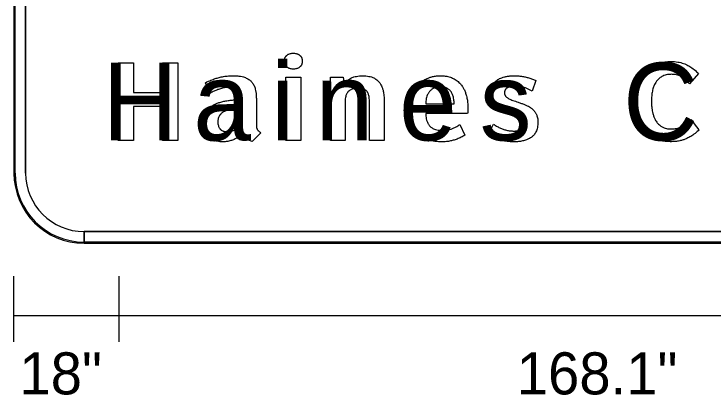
# Model space of a CAD drawing. Extents: x 10268259 to 10268554, y 2141099 to 2141249.
# Drawn here: x 10268434.65 to 10268446.62, y 2141129.23 to 2141135.75 of the extents above; entities that cross this region are included whole.
import ezdxf

# ---------------------------------------------------------------- set-up
doc = ezdxf.new("R2010")
doc.units = 0
for name, color, linetype in [('GSBWFill', 7, 'Continuous'), ('GSColorFill', 7, 'Continuous'), ('GSDims', 7, 'Continuous'), ('GSOutline', 7, 'Continuous')]:
    doc.layers.add(name, color=color, linetype=linetype)

msp = doc.modelspace()

# ---------------------------------------------------------------- linework, layer by layer
at = {"layer": 'GSBWFill'}
for p, q in [((10268434.654, 2141148.028), (10268434.654, 2141133.028)), ((10268434.854, 2141133.028), (10268434.854, 2141148.028)), ((10268435.854, 2141131.828), (10268435.854, 2141132.028)), ((10268453.854, 2141132.028), (10268435.856, 2141132.028)), ((10268435.856, 2141132.028), (10268435.856, 2141131.828)), ((10268435.856, 2141131.828), (10268453.854, 2141131.828))]:
    msp.add_line(p, q, dxfattribs=at)
for radius in [1.2, 1]:
    msp.add_arc((10268435.854, 2141133.028), radius, 180, 270, dxfattribs=at)
at = {"layer": 'GSColorFill'}
for p, q in [((10268434.654, 2141148.028), (10268434.654, 2141133.028)), ((10268434.654, 2141148.028), (10268434.654, 2141133.028)), ((10268434.654, 2141148.028), (10268434.654, 2141133.028)), ((10268434.674, 2141133.028), (10268434.674, 2141148.028)), ((10268434.854, 2141133.028), (10268434.854, 2141148.028)), ((10268435.854, 2141131.828), (10268435.854, 2141132.028)), ((10268453.854, 2141132.028), (10268435.856, 2141132.028)), ((10268435.856, 2141132.028), (10268435.856, 2141131.828)), ((10268435.854, 2141131.828), (10268435.854, 2141131.848)), ((10268453.854, 2141131.848), (10268435.855, 2141131.848)), ((10268435.855, 2141131.848), (10268435.855, 2141131.828)), ((10268435.854, 2141131.828), (10268453.854, 2141131.828)), ((10268435.855, 2141131.828), (10268453.854, 2141131.828)), ((10268435.856, 2141131.828), (10268453.854, 2141131.828))]:
    msp.add_line(p, q, dxfattribs=at)
for radius in [1.2, 1.2, 1.2, 1.18, 1]:
    msp.add_arc((10268435.854, 2141133.028), radius, 180, 270, dxfattribs=at)
at = {"layer": 'GSDims'}
for p, q in [((10268434.654, 2141130.139), (10268434.654, 2141131.264)), ((10268436.454, 2141130.139), (10268436.454, 2141131.264)), ((10268434.654, 2141130.589), (10268455.054, 2141130.589))]:
    msp.add_line(p, q, dxfattribs=at)
at = {"layer": 'GSOutline'}
for p, q in [((10268434.654, 2141148.028), (10268434.654, 2141133.028)), ((10268434.854, 2141148.028), (10268434.854, 2141133.028)), ((10268435.854, 2141132.028), (10268453.854, 2141132.028)), ((10268435.854, 2141131.828), (10268453.854, 2141131.828))]:
    msp.add_line(p, q, dxfattribs=at)
for points in [[(10268437.199, 2141133.588), (10268437.199, 2141134.167), (10268436.698, 2141134.167), (10268436.698, 2141133.588), (10268436.438, 2141133.588), (10268436.438, 2141134.918), (10268436.698, 2141134.918), (10268436.698, 2141134.411), (10268437.199, 2141134.411), (10268437.199, 2141134.918), (10268437.457, 2141134.918), (10268437.457, 2141133.588), (10268437.199, 2141133.588)], [(10268446.37, 2141134.735), (10268446.213, 2141134.559)], [(10268439.308, 2141133.588), (10268439.308, 2141134.674), (10268439.563, 2141134.674), (10268439.563, 2141133.588), (10268439.308, 2141133.588)], [(10268440.321, 2141134.246), (10268440.321, 2141133.588), (10268440.069, 2141133.588), (10268440.069, 2141134.674), (10268440.288, 2141134.674), (10268440.308, 2141134.553), (10268440.312, 2141134.553)], [(10268443.586, 2141134.612), (10268443.521, 2141134.432)], [(10268438.005, 2141134.393), (10268437.93, 2141134.576)], [(10268438.555, 2141134.286), (10268438.555, 2141134.335)], [(10268438.803, 2141134.294), (10268438.803, 2141133.861)], [(10268440.991, 2141134.242), (10268440.991, 2141133.588), (10268440.739, 2141133.588)], [(10268438.552, 2141133.841), (10268438.552, 2141134.133)], [(10268440.739, 2141133.588), (10268440.739, 2141134.203)], [(10268441.702, 2141134.214), (10268442.187, 2141134.214)], [(10268442.419, 2141134.048), (10268441.702, 2141134.048)], [(10268446.238, 2141133.945), (10268446.376, 2141133.768)], [(10268442.284, 2141133.859), (10268442.368, 2141133.677)], [(10268442.77, 2141133.686), (10268442.86, 2141133.865)], [(10268438.579, 2141133.7), (10268438.575, 2141133.7)], [(10268438.882, 2141133.72), (10268438.731, 2141133.572)]]:
    msp.add_lwpolyline(points, dxfattribs=at)
for radius in [1.2, 1]:
    msp.add_arc((10268435.854, 2141133.028), radius, 180, 270, dxfattribs=at)
for points in [[(10268439.282, 2141134.946), (10268439.282, 2141134.951), (10268439.282, 2141134.963), (10268439.285, 2141134.979), (10268439.29, 2141134.995), (10268439.295, 2141135.007), (10268439.301, 2141135.019), (10268439.309, 2141135.03), (10268439.316, 2141135.038), (10268439.323, 2141135.044), (10268439.33, 2141135.05), (10268439.339, 2141135.057), (10268439.358, 2141135.068), (10268439.384, 2141135.077), (10268439.413, 2141135.081), (10268439.43, 2141135.081), (10268439.435, 2141135.082)], [(10268439.435, 2141135.082), (10268439.441, 2141135.081), (10268439.457, 2141135.081), (10268439.483, 2141135.077), (10268439.505, 2141135.07), (10268439.521, 2141135.063), (10268439.531, 2141135.057), (10268439.54, 2141135.05), (10268439.547, 2141135.044), (10268439.554, 2141135.038), (10268439.562, 2141135.03), (10268439.569, 2141135.019), (10268439.576, 2141135.007), (10268439.581, 2141134.995), (10268439.586, 2141134.979), (10268439.589, 2141134.963), (10268439.589, 2141134.951), (10268439.589, 2141134.946)], [(10268439.435, 2141134.81), (10268439.43, 2141134.81), (10268439.413, 2141134.81), (10268439.387, 2141134.814), (10268439.365, 2141134.821), (10268439.349, 2141134.828), (10268439.339, 2141134.834), (10268439.33, 2141134.84), (10268439.323, 2141134.846), (10268439.316, 2141134.852), (10268439.309, 2141134.86), (10268439.301, 2141134.871), (10268439.295, 2141134.883), (10268439.289, 2141134.895), (10268439.285, 2141134.911), (10268439.282, 2141134.928), (10268439.282, 2141134.941), (10268439.282, 2141134.946)], [(10268439.589, 2141134.946), (10268439.589, 2141134.941), (10268439.589, 2141134.928), (10268439.586, 2141134.911), (10268439.581, 2141134.895), (10268439.576, 2141134.883), (10268439.569, 2141134.871), (10268439.562, 2141134.86), (10268439.554, 2141134.852), (10268439.547, 2141134.846), (10268439.54, 2141134.84), (10268439.529, 2141134.832), (10268439.51, 2141134.822), (10268439.483, 2141134.814), (10268439.457, 2141134.81), (10268439.441, 2141134.81), (10268439.435, 2141134.81)], [(10268445.292, 2141134.259), (10268445.293, 2141134.282), (10268445.294, 2141134.351), (10268445.307, 2141134.442), (10268445.329, 2141134.527), (10268445.354, 2141134.597), (10268445.386, 2141134.662), (10268445.42, 2141134.713), (10268445.445, 2141134.744), (10268445.471, 2141134.774), (10268445.507, 2141134.808), (10268445.556, 2141134.844), (10268445.599, 2141134.87), (10268445.636, 2141134.888), (10268445.676, 2141134.904), (10268445.74, 2141134.924), (10268445.82, 2141134.937), (10268445.88, 2141134.939), (10268445.905, 2141134.939)], [(10268445.905, 2141134.939), (10268445.927, 2141134.939), (10268445.961, 2141134.938), (10268446.015, 2141134.931), (10268446.066, 2141134.921), (10268446.116, 2141134.905), (10268446.154, 2141134.89), (10268446.221, 2141134.857), (10268446.295, 2141134.805), (10268446.352, 2141134.751), (10268446.37, 2141134.735)], [(10268445.91, 2141134.72), (10268445.897, 2141134.719), (10268445.863, 2141134.718), (10268445.818, 2141134.711), (10268445.777, 2141134.698), (10268445.744, 2141134.683), (10268445.714, 2141134.665), (10268445.687, 2141134.643), (10268445.667, 2141134.621), (10268445.652, 2141134.603), (10268445.638, 2141134.582), (10268445.618, 2141134.549), (10268445.594, 2141134.491), (10268445.575, 2141134.41), (10268445.566, 2141134.329), (10268445.565, 2141134.277), (10268445.565, 2141134.258)], [(10268446.213, 2141134.559), (10268446.202, 2141134.572), (10268446.169, 2141134.607), (10268446.121, 2141134.647), (10268446.078, 2141134.676), (10268446.048, 2141134.692), (10268446.016, 2141134.705), (10268445.976, 2141134.715), (10268445.94, 2141134.719), (10268445.918, 2141134.719), (10268445.91, 2141134.72)], [(10268437.93, 2141134.576), (10268437.969, 2141134.594), (10268438.026, 2141134.621), (10268438.103, 2141134.648), (10268438.161, 2141134.665), (10268438.24, 2141134.684), (10268438.322, 2141134.694), (10268438.385, 2141134.695), (10268438.406, 2141134.695)], [(10268438.406, 2141134.695), (10268438.424, 2141134.695), (10268438.472, 2141134.694), (10268438.535, 2141134.687), (10268438.584, 2141134.674), (10268438.615, 2141134.663), (10268438.644, 2141134.651), (10268438.675, 2141134.632), (10268438.698, 2141134.614), (10268438.714, 2141134.598), (10268438.73, 2141134.581), (10268438.747, 2141134.558), (10268438.764, 2141134.526), (10268438.775, 2141134.498), (10268438.784, 2141134.467), (10268438.795, 2141134.418), (10268438.802, 2141134.357), (10268438.802, 2141134.311), (10268438.803, 2141134.294)], [(10268440.312, 2141134.553), (10268440.316, 2141134.559), (10268440.33, 2141134.578), (10268440.355, 2141134.607), (10268440.388, 2141134.635), (10268440.418, 2141134.654), (10268440.444, 2141134.665), (10268440.471, 2141134.674), (10268440.513, 2141134.686), (10268440.566, 2141134.694), (10268440.604, 2141134.695), (10268440.62, 2141134.695)], [(10268440.62, 2141134.695), (10268440.638, 2141134.695), (10268440.678, 2141134.694), (10268440.732, 2141134.686), (10268440.774, 2141134.674), (10268440.799, 2141134.664), (10268440.822, 2141134.653), (10268440.849, 2141134.638), (10268440.878, 2141134.615), (10268440.899, 2141134.593), (10268440.914, 2141134.574), (10268440.928, 2141134.553), (10268440.943, 2141134.526), (10268440.961, 2141134.483), (10268440.974, 2141134.437), (10268440.988, 2141134.354), (10268440.99, 2141134.291), (10268440.991, 2141134.242)], [(10268441.444, 2141134.13), (10268441.444, 2141134.154), (10268441.445, 2141134.219), (10268441.457, 2141134.294), (10268441.474, 2141134.353), (10268441.486, 2141134.389), (10268441.507, 2141134.439), (10268441.538, 2141134.492), (10268441.569, 2141134.532), (10268441.592, 2141134.557), (10268441.615, 2141134.579), (10268441.646, 2141134.605), (10268441.687, 2141134.631), (10268441.723, 2141134.649), (10268441.762, 2141134.664), (10268441.818, 2141134.682), (10268441.886, 2141134.694), (10268441.938, 2141134.695), (10268441.955, 2141134.695)], [(10268441.955, 2141134.695), (10268441.974, 2141134.695), (10268442.019, 2141134.694), (10268442.079, 2141134.684), (10268442.128, 2141134.669), (10268442.158, 2141134.657), (10268442.186, 2141134.643), (10268442.22, 2141134.624), (10268442.256, 2141134.596), (10268442.284, 2141134.569), (10268442.304, 2141134.546), (10268442.323, 2141134.521), (10268442.35, 2141134.48), (10268442.375, 2141134.426), (10268442.394, 2141134.368), (10268442.412, 2141134.295), (10268442.422, 2141134.216), (10268442.423, 2141134.155), (10268442.423, 2141134.134)], [(10268442.808, 2141134.388), (10268442.808, 2141134.394), (10268442.809, 2141134.412), (10268442.812, 2141134.44), (10268442.818, 2141134.473), (10268442.827, 2141134.499), (10268442.836, 2141134.518), (10268442.846, 2141134.537), (10268442.86, 2141134.559), (10268442.88, 2141134.583), (10268442.9, 2141134.602), (10268442.917, 2141134.615), (10268442.935, 2141134.628), (10268442.965, 2141134.646), (10268443.003, 2141134.662), (10268443.045, 2141134.675), (10268443.099, 2141134.688), (10268443.157, 2141134.694), (10268443.201, 2141134.695), (10268443.216, 2141134.695)], [(10268443.216, 2141134.695), (10268443.232, 2141134.695), (10268443.28, 2141134.694), (10268443.343, 2141134.687), (10268443.405, 2141134.676), (10268443.467, 2141134.661), (10268443.528, 2141134.639), (10268443.571, 2141134.619), (10268443.586, 2141134.612)], [(10268438.387, 2141134.503), (10268438.37, 2141134.503), (10268438.32, 2141134.502), (10268438.253, 2141134.491), (10268438.188, 2141134.474), (10268438.125, 2141134.452), (10268438.063, 2141134.425), (10268438.02, 2141134.401), (10268438.005, 2141134.393)], [(10268438.555, 2141134.335), (10268438.555, 2141134.342), (10268438.554, 2141134.362), (10268438.551, 2141134.392), (10268438.544, 2141134.418), (10268438.537, 2141134.435), (10268438.531, 2141134.446), (10268438.525, 2141134.456), (10268438.519, 2141134.463), (10268438.513, 2141134.47), (10268438.503, 2141134.477), (10268438.49, 2141134.485), (10268438.473, 2141134.492), (10268438.446, 2141134.499), (10268438.416, 2141134.503), (10268438.395, 2141134.503), (10268438.387, 2141134.503)], [(10268440.547, 2141134.482), (10268440.538, 2141134.482), (10268440.511, 2141134.481), (10268440.473, 2141134.476), (10268440.439, 2141134.466), (10268440.416, 2141134.455), (10268440.398, 2141134.444), (10268440.385, 2141134.434), (10268440.375, 2141134.424), (10268440.366, 2141134.414), (10268440.356, 2141134.4), (10268440.346, 2141134.382), (10268440.336, 2141134.358), (10268440.326, 2141134.322), (10268440.321, 2141134.283), (10268440.321, 2141134.255), (10268440.321, 2141134.246)], [(10268440.739, 2141134.203), (10268440.739, 2141134.223), (10268440.739, 2141134.26), (10268440.736, 2141134.306), (10268440.731, 2141134.343), (10268440.725, 2141134.37), (10268440.717, 2141134.391), (10268440.711, 2141134.404), (10268440.704, 2141134.416), (10268440.694, 2141134.43), (10268440.679, 2141134.444), (10268440.665, 2141134.454), (10268440.653, 2141134.462), (10268440.639, 2141134.468), (10268440.619, 2141134.475), (10268440.587, 2141134.481), (10268440.563, 2141134.482), (10268440.547, 2141134.482)], [(10268441.956, 2141134.505), (10268441.946, 2141134.504), (10268441.923, 2141134.504), (10268441.892, 2141134.499), (10268441.863, 2141134.491), (10268441.84, 2141134.481), (10268441.818, 2141134.47), (10268441.798, 2141134.456), (10268441.782, 2141134.442), (10268441.77, 2141134.43), (10268441.759, 2141134.417), (10268441.747, 2141134.4), (10268441.734, 2141134.377), (10268441.721, 2141134.347), (10268441.709, 2141134.304), (10268441.703, 2141134.258), (10268441.702, 2141134.226), (10268441.702, 2141134.214)], [(10268442.187, 2141134.214), (10268442.187, 2141134.224), (10268442.186, 2141134.253), (10268442.182, 2141134.291), (10268442.175, 2141134.327), (10268442.167, 2141134.361), (10268442.155, 2141134.388), (10268442.143, 2141134.41), (10268442.137, 2141134.42), (10268442.127, 2141134.433), (10268442.114, 2141134.448), (10268442.096, 2141134.463), (10268442.08, 2141134.474), (10268442.065, 2141134.482), (10268442.05, 2141134.489), (10268442.029, 2141134.496), (10268441.996, 2141134.503), (10268441.971, 2141134.504), (10268441.956, 2141134.505)], [(10268443.235, 2141134.518), (10268443.222, 2141134.517), (10268443.192, 2141134.517), (10268443.151, 2141134.51), (10268443.12, 2141134.5), (10268443.104, 2141134.493), (10268443.093, 2141134.487), (10268443.084, 2141134.481), (10268443.074, 2141134.472), (10268443.065, 2141134.462), (10268443.059, 2141134.451), (10268443.054, 2141134.439), (10268443.051, 2141134.425), (10268443.049, 2141134.413), (10268443.049, 2141134.406), (10268443.049, 2141134.403)], [(10268443.521, 2141134.432), (10268443.51, 2141134.439), (10268443.478, 2141134.458), (10268443.433, 2141134.479), (10268443.385, 2141134.495), (10268443.337, 2141134.509), (10268443.286, 2141134.516), (10268443.248, 2141134.517), (10268443.235, 2141134.518)], [(10268443.138, 2141134.054), (10268443.118, 2141134.061), (10268443.079, 2141134.074), (10268443.03, 2141134.092), (10268442.983, 2141134.113), (10268442.948, 2141134.134), (10268442.919, 2141134.155), (10268442.9, 2141134.171), (10268442.882, 2141134.188), (10268442.859, 2141134.215), (10268442.843, 2141134.241), (10268442.828, 2141134.27), (10268442.819, 2141134.296), (10268442.812, 2141134.331), (10268442.809, 2141134.362), (10268442.808, 2141134.381), (10268442.808, 2141134.388)], [(10268443.049, 2141134.403), (10268443.049, 2141134.4), (10268443.049, 2141134.393), (10268443.051, 2141134.38), (10268443.056, 2141134.366), (10268443.062, 2141134.355), (10268443.068, 2141134.347), (10268443.074, 2141134.339), (10268443.086, 2141134.328), (10268443.101, 2141134.316), (10268443.124, 2141134.302), (10268443.154, 2141134.287), (10268443.193, 2141134.272), (10268443.236, 2141134.258), (10268443.265, 2141134.248), (10268443.281, 2141134.243)], [(10268437.896, 2141133.893), (10268437.896, 2141133.907), (10268437.897, 2141133.928), (10268437.901, 2141133.961), (10268437.907, 2141133.992), (10268437.916, 2141134.021), (10268437.928, 2141134.047), (10268437.939, 2141134.067), (10268437.954, 2141134.091), (10268437.971, 2141134.113), (10268437.99, 2141134.133), (10268438.01, 2141134.152), (10268438.041, 2141134.177), (10268438.081, 2141134.201), (10268438.134, 2141134.225), (10268438.191, 2141134.245), (10268438.263, 2141134.262), (10268438.336, 2141134.274), (10268438.41, 2141134.282), (10268438.483, 2141134.286), (10268438.531, 2141134.286), (10268438.555, 2141134.286)], [(10268443.281, 2141134.243), (10268443.301, 2141134.236), (10268443.341, 2141134.223), (10268443.391, 2141134.204), (10268443.44, 2141134.183), (10268443.477, 2141134.162), (10268443.507, 2141134.14), (10268443.527, 2141134.124), (10268443.545, 2141134.106), (10268443.566, 2141134.082), (10268443.58, 2141134.06), (10268443.591, 2141134.042), (10268443.601, 2141134.022), (10268443.61, 2141133.995), (10268443.618, 2141133.959), (10268443.621, 2141133.927), (10268443.621, 2141133.907), (10268443.621, 2141133.9)], [(10268445.905, 2141133.566), (10268445.879, 2141133.566), (10268445.818, 2141133.568), (10268445.735, 2141133.581), (10268445.67, 2141133.6), (10268445.63, 2141133.617), (10268445.592, 2141133.634), (10268445.548, 2141133.66), (10268445.5, 2141133.696), (10268445.465, 2141133.73), (10268445.439, 2141133.76), (10268445.414, 2141133.791), (10268445.381, 2141133.842), (10268445.35, 2141133.908), (10268445.327, 2141133.979), (10268445.306, 2141134.068), (10268445.294, 2141134.162), (10268445.293, 2141134.234), (10268445.292, 2141134.259)], [(10268445.565, 2141134.258), (10268445.566, 2141134.227), (10268445.567, 2141134.179), (10268445.575, 2141134.118), (10268445.583, 2141134.074), (10268445.596, 2141134.019), (10268445.615, 2141133.969), (10268445.637, 2141133.928), (10268445.654, 2141133.902), (10268445.674, 2141133.878), (10268445.7, 2141133.852), (10268445.725, 2141133.834), (10268445.746, 2141133.821), (10268445.769, 2141133.809), (10268445.8, 2141133.797), (10268445.841, 2141133.788), (10268445.877, 2141133.784), (10268445.9, 2141133.784), (10268445.908, 2141133.784)], [(10268438.552, 2141134.133), (10268438.531, 2141134.133), (10268438.486, 2141134.132), (10268438.43, 2141134.128), (10268438.373, 2141134.122), (10268438.328, 2141134.113), (10268438.291, 2141134.101), (10268438.266, 2141134.091), (10268438.243, 2141134.079), (10268438.217, 2141134.062), (10268438.198, 2141134.046), (10268438.185, 2141134.033), (10268438.177, 2141134.023), (10268438.17, 2141134.013), (10268438.158, 2141133.993), (10268438.148, 2141133.964), (10268438.144, 2141133.932), (10268438.143, 2141133.914), (10268438.143, 2141133.908)], [(10268441.968, 2141133.564), (10268441.948, 2141133.565), (10268441.898, 2141133.566), (10268441.831, 2141133.576), (10268441.777, 2141133.592), (10268441.743, 2141133.604), (10268441.711, 2141133.618), (10268441.674, 2141133.639), (10268441.633, 2141133.667), (10268441.601, 2141133.695), (10268441.578, 2141133.719), (10268441.557, 2141133.744), (10268441.532, 2141133.778), (10268441.502, 2141133.831), (10268441.479, 2141133.889), (10268441.456, 2141133.971), (10268441.445, 2141134.049), (10268441.444, 2141134.109), (10268441.444, 2141134.13)], [(10268442.423, 2141134.134), (10268442.423, 2141134.128), (10268442.423, 2141134.115), (10268442.422, 2141134.094), (10268442.421, 2141134.072), (10268442.42, 2141134.056), (10268442.419, 2141134.048)], [(10268441.702, 2141134.048), (10268441.702, 2141134.036), (10268441.703, 2141134.004), (10268441.71, 2141133.954), (10268441.724, 2141133.912), (10268441.737, 2141133.883), (10268441.748, 2141133.864), (10268441.76, 2141133.847), (10268441.771, 2141133.834), (10268441.783, 2141133.822), (10268441.799, 2141133.808), (10268441.821, 2141133.794), (10268441.849, 2141133.78), (10268441.892, 2141133.767), (10268441.938, 2141133.76), (10268441.97, 2141133.76), (10268441.982, 2141133.76)], [(10268443.377, 2141133.881), (10268443.377, 2141133.884), (10268443.377, 2141133.893), (10268443.375, 2141133.907), (10268443.37, 2141133.923), (10268443.364, 2141133.935), (10268443.357, 2141133.944), (10268443.35, 2141133.952), (10268443.338, 2141133.965), (10268443.322, 2141133.978), (10268443.298, 2141133.993), (10268443.267, 2141134.008), (10268443.227, 2141134.024), (10268443.183, 2141134.039), (10268443.153, 2141134.049), (10268443.138, 2141134.054)], [(10268438.22, 2141133.564), (10268438.208, 2141133.564), (10268438.173, 2141133.565), (10268438.132, 2141133.572), (10268438.1, 2141133.582), (10268438.085, 2141133.587), (10268438.065, 2141133.595), (10268438.042, 2141133.607), (10268438.017, 2141133.624), (10268437.997, 2141133.64), (10268437.983, 2141133.654), (10268437.969, 2141133.668), (10268437.954, 2141133.688), (10268437.935, 2141133.719), (10268437.919, 2141133.753), (10268437.905, 2141133.801), (10268437.897, 2141133.846), (10268437.896, 2141133.881), (10268437.896, 2141133.893)], [(10268438.143, 2141133.908), (10268438.143, 2141133.902), (10268438.144, 2141133.885), (10268438.147, 2141133.857), (10268438.157, 2141133.826), (10268438.168, 2141133.803), (10268438.179, 2141133.788), (10268438.187, 2141133.779), (10268438.195, 2141133.77), (10268438.207, 2141133.761), (10268438.22, 2141133.753), (10268438.235, 2141133.747), (10268438.253, 2141133.742), (10268438.273, 2141133.739), (10268438.288, 2141133.739), (10268438.295, 2141133.739)], [(10268443.206, 2141133.748), (10268443.212, 2141133.748), (10268443.231, 2141133.749), (10268443.261, 2141133.752), (10268443.293, 2141133.759), (10268443.314, 2141133.768), (10268443.327, 2141133.776), (10268443.333, 2141133.779), (10268443.34, 2141133.785), (10268443.348, 2141133.792), (10268443.356, 2141133.803), (10268443.363, 2141133.814), (10268443.369, 2141133.827), (10268443.374, 2141133.843), (10268443.377, 2141133.862), (10268443.377, 2141133.875), (10268443.377, 2141133.881)], [(10268443.621, 2141133.9), (10268443.621, 2141133.886), (10268443.62, 2141133.853), (10268443.613, 2141133.808), (10268443.601, 2141133.766), (10268443.588, 2141133.734), (10268443.571, 2141133.705), (10268443.55, 2141133.678), (10268443.53, 2141133.659), (10268443.513, 2141133.645), (10268443.494, 2141133.632), (10268443.464, 2141133.614), (10268443.412, 2141133.591), (10268443.341, 2141133.573), (10268443.27, 2141133.565), (10268443.224, 2141133.564), (10268443.209, 2141133.564)], [(10268445.908, 2141133.784), (10268445.916, 2141133.784), (10268445.939, 2141133.784), (10268445.977, 2141133.789), (10268446.02, 2141133.798), (10268446.055, 2141133.811), (10268446.088, 2141133.827), (10268446.136, 2141133.855), (10268446.189, 2141133.896), (10268446.225, 2141133.932), (10268446.238, 2141133.945)], [(10268438.295, 2141133.739), (10268438.3, 2141133.739), (10268438.318, 2141133.739), (10268438.347, 2141133.742), (10268438.381, 2141133.749), (10268438.409, 2141133.758), (10268438.435, 2141133.769), (10268438.473, 2141133.786), (10268438.514, 2141133.811), (10268438.542, 2141133.833), (10268438.552, 2141133.841)], [(10268438.803, 2141133.861), (10268438.803, 2141133.852), (10268438.803, 2141133.839), (10268438.805, 2141133.822), (10268438.806, 2141133.812), (10268438.809, 2141133.799), (10268438.814, 2141133.787), (10268438.819, 2141133.775), (10268438.825, 2141133.765), (10268438.834, 2141133.755), (10268438.843, 2141133.746), (10268438.858, 2141133.734), (10268438.872, 2141133.726), (10268438.882, 2141133.72)], [(10268441.982, 2141133.76), (10268441.995, 2141133.76), (10268442.035, 2141133.761), (10268442.086, 2141133.768), (10268442.134, 2141133.782), (10268442.184, 2141133.801), (10268442.235, 2141133.827), (10268442.271, 2141133.851), (10268442.284, 2141133.859)], [(10268442.86, 2141133.865), (10268442.873, 2141133.857), (10268442.912, 2141133.832), (10268442.967, 2141133.805), (10268443.025, 2141133.781), (10268443.084, 2141133.762), (10268443.145, 2141133.75), (10268443.19, 2141133.749), (10268443.206, 2141133.748)], [(10268446.376, 2141133.768), (10268446.359, 2141133.752), (10268446.31, 2141133.705), (10268446.236, 2141133.654), (10268446.168, 2141133.62), (10268446.119, 2141133.6), (10268446.068, 2141133.584), (10268445.993, 2141133.569), (10268445.938, 2141133.567), (10268445.905, 2141133.566)], [(10268438.575, 2141133.7), (10268438.562, 2141133.69), (10268438.524, 2141133.659), (10268438.468, 2141133.626), (10268438.41, 2141133.599), (10268438.349, 2141133.578), (10268438.285, 2141133.566), (10268438.236, 2141133.565), (10268438.22, 2141133.564)], [(10268438.731, 2141133.572), (10268438.722, 2141133.575), (10268438.7, 2141133.58), (10268438.671, 2141133.592), (10268438.648, 2141133.605), (10268438.634, 2141133.615), (10268438.621, 2141133.625), (10268438.606, 2141133.64), (10268438.592, 2141133.662), (10268438.584, 2141133.682), (10268438.58, 2141133.695), (10268438.579, 2141133.7)], [(10268442.368, 2141133.677), (10268442.352, 2141133.667), (10268442.305, 2141133.64), (10268442.239, 2141133.61), (10268442.173, 2141133.589), (10268442.107, 2141133.574), (10268442.038, 2141133.565), (10268441.986, 2141133.564), (10268441.968, 2141133.564)], [(10268443.209, 2141133.564), (10268443.189, 2141133.564), (10268443.131, 2141133.566), (10268443.055, 2141133.576), (10268442.98, 2141133.594), (10268442.907, 2141133.617), (10268442.836, 2141133.647), (10268442.786, 2141133.676), (10268442.77, 2141133.686)]]:
    msp.add_open_spline(points, degree=3, dxfattribs=at)

# ---------------------------------------------------------------- texts
at = {"layer": 'GSBWFill'}
for s, p in [('i', (10268439.056, 2141133.588)), ('H', (10268436.171, 2141133.588)), ('C', (10268445.079, 2141133.588)), ('a', (10268437.723, 2141133.588)), ('n', (10268439.816, 2141133.588)), ('e', (10268441.245, 2141133.588)), ('s', (10268442.624, 2141133.588))]:
    msp.add_text(s, height=1.33, rotation=360, dxfattribs=at).set_placement(p)
at = {"layer": 'GSColorFill'}
for s, p in [('i', (10268439.056, 2141133.588)), ('H', (10268436.171, 2141133.588)), ('C', (10268445.079, 2141133.588)), ('a', (10268437.723, 2141133.588)), ('n', (10268439.816, 2141133.588)), ('e', (10268441.245, 2141133.588)), ('s', (10268442.624, 2141133.588))]:
    msp.add_text(s, height=1.33, rotation=360, dxfattribs=at).set_placement(p)
at = {"layer": 'GSDims'}
for s, p in [('18"', (10268434.747, 2141129.239)), ('168.1"', (10268443.259, 2141129.239))]:
    msp.add_text(s, height=0.72, dxfattribs=at).set_placement(p)

doc.saveas('drawing.dxf')
